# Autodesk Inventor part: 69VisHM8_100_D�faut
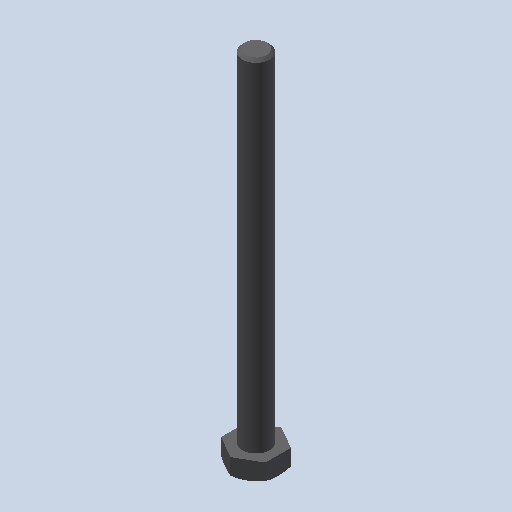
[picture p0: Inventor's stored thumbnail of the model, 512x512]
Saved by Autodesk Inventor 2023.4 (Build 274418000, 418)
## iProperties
Created: 2011-01
Part Number: 69VisHM8_100_D�faut
Document SubType Name: Modeling
Designer: eric
Density: 1 g/cm^3
Mass: 5.79236 g
Surface Area: 30.252 cm^2
Volume: 5.79236 cm^3
Material: Générique
Appearance: Red
Author: eric
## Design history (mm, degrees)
feature "Base1"
node "Corps solides"
node "Corps surfaciques"
node "Solide1"
